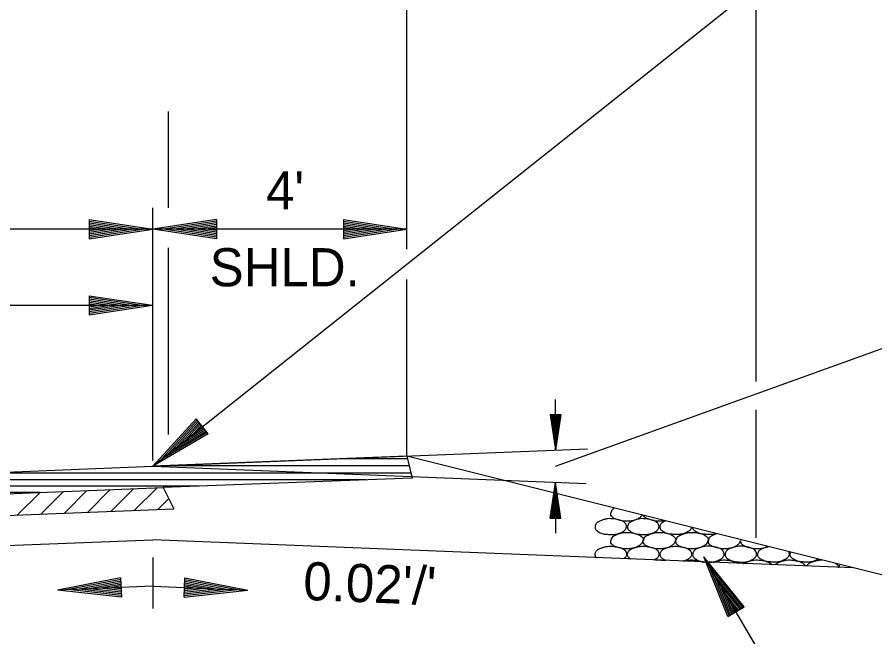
# Model space of a CAD drawing. Extents: x 1955768 to 1955917, y 566446 to 566546.
# Drawn here: x 1955845.04 to 1955858.54, y 566463.92 to 566473.67 of the extents above; entities that cross this region are included whole.
import ezdxf

# ---------------------------------------------------------------- set-up
doc = ezdxf.new("R2010")
doc.units = 0
doc.layers.add('R_Border', color=7, linetype='Continuous')
doc.layers.add('R_Grid', color=7, linetype='Continuous')

msp = doc.modelspace()

# ---------------------------------------------------------------- linework, layer by layer
at = {"layer": 'R_Border'}
for p, q in [((1955847.173, 566466.604), (1955854.018, 566466.878)), ((1955851.173, 566466.764), (1955847.173, 566466.604)), ((1955864.818, 566463.353), (1955851.173, 566466.764)), ((1955851.173, 566466.764), (1955851.259, 566466.42)), ((1955826.173, 566465.764), (1955847.173, 566466.604)), ((1955847.173, 566466.604), (1955853.996, 566466.331)), ((1955851.259, 566466.42), (1955847.339, 566466.271)), ((1955826.087, 566465.42), (1955847.339, 566466.271)), ((1955847.339, 566466.271), (1955847.506, 566465.937)), ((1955847.339, 566466.271), (1955847.506, 566465.937)), ((1955831.826, 566465.309), (1955847.506, 566465.937)), ((1955820.673, 566464.389), (1955847.173, 566465.449)), ((1955858.197, 566465.008), (1955847.173, 566465.449))]:
    msp.add_line(p, q, dxfattribs=at)
msp.add_lwpolyline([(1955853.512, 566466.604), (1955861.743, 566469.569)], dxfattribs=at)
at = {"layer": 'R_Grid'}
for p, q in [((1955851.173, 566470.021), (1955851.173, 566476.637)), ((1955856.673, 566467.941), (1955856.673, 566474.004)), ((1955847.423, 566470.669), (1955847.423, 566472.187)), ((1955847.173, 566466.694), (1955847.173, 566470.669)), ((1955846.173, 566470.486), (1955847.173, 566470.336)), ((1955846.173, 566470.486), (1955846.173, 566470.186)), ((1955846.173, 566470.461), (1955847.006, 566470.336)), ((1955848.174, 566470.486), (1955847.174, 566470.336)), ((1955848.174, 566470.461), (1955847.341, 566470.336)), ((1955848.174, 566470.486), (1955848.174, 566470.186)), ((1955850.173, 566470.486), (1955851.173, 566470.336)), ((1955850.173, 566470.486), (1955850.173, 566470.186)), ((1955850.173, 566470.461), (1955851.006, 566470.336)), ((1955847.173, 566470.336), (1955832.173, 566470.336)), ((1955846.173, 566470.436), (1955846.834, 566470.336)), ((1955846.173, 566470.411), (1955846.667, 566470.336)), ((1955846.173, 566470.385), (1955846.498, 566470.336)), ((1955846.173, 566470.36), (1955846.331, 566470.336)), ((1955846.173, 566470.186), (1955847.173, 566470.336)), ((1955846.173, 566470.287), (1955846.498, 566470.336)), ((1955846.173, 566470.237), (1955846.834, 566470.336)), ((1955846.173, 566470.211), (1955847.006, 566470.336)), ((1955846.173, 566470.262), (1955846.667, 566470.336)), ((1955846.173, 566470.313), (1955846.331, 566470.336)), ((1955851.173, 566470.336), (1955847.173, 566470.336)), ((1955848.174, 566470.186), (1955847.174, 566470.336)), ((1955848.174, 566470.211), (1955847.341, 566470.336)), ((1955848.174, 566470.436), (1955847.513, 566470.336)), ((1955848.174, 566470.237), (1955847.513, 566470.336)), ((1955848.174, 566470.411), (1955847.68, 566470.336)), ((1955848.174, 566470.262), (1955847.68, 566470.336)), ((1955848.174, 566470.385), (1955847.849, 566470.336)), ((1955848.174, 566470.287), (1955847.849, 566470.336)), ((1955848.174, 566470.36), (1955848.016, 566470.336)), ((1955848.174, 566470.313), (1955848.016, 566470.336)), ((1955850.799, 566470.336), (1955849.173, 566470.336)), ((1955850.173, 566470.436), (1955850.834, 566470.336)), ((1955850.173, 566470.411), (1955850.667, 566470.336)), ((1955850.173, 566470.385), (1955850.498, 566470.336)), ((1955850.173, 566470.36), (1955850.331, 566470.336)), ((1955850.173, 566470.186), (1955851.173, 566470.336)), ((1955850.173, 566470.287), (1955850.498, 566470.336)), ((1955850.173, 566470.237), (1955850.834, 566470.336)), ((1955850.173, 566470.211), (1955851.006, 566470.336)), ((1955850.173, 566470.262), (1955850.667, 566470.336)), ((1955850.173, 566470.313), (1955850.331, 566470.336)), ((1955847.423, 566467.104), (1955847.423, 566470.043)), ((1955851.173, 566466.762), (1955851.173, 566469.542)), ((1955846.171, 566469.289), (1955847.171, 566469.139)), ((1955846.171, 566469.289), (1955846.171, 566468.989)), ((1955846.171, 566469.264), (1955847.004, 566469.139)), ((1955846.171, 566469.238), (1955846.832, 566469.139)), ((1955839.673, 566469.139), (1955847.173, 566469.139)), ((1955846.171, 566469.213), (1955846.666, 566469.139)), ((1955846.171, 566469.187), (1955846.496, 566469.139)), ((1955846.171, 566469.162), (1955846.329, 566469.139)), ((1955846.171, 566468.989), (1955847.171, 566469.139)), ((1955846.171, 566469.09), (1955846.496, 566469.139)), ((1955846.171, 566469.039), (1955846.832, 566469.139)), ((1955846.171, 566469.014), (1955847.004, 566469.139)), ((1955846.171, 566469.064), (1955846.666, 566469.139)), ((1955846.171, 566469.115), (1955846.329, 566469.139)), ((1955853.512, 566466.858), (1955853.512, 566467.654)), ((1955856.673, 566465.48), (1955856.673, 566467.491)), ((1955847.857, 566467.349), (1955847.173, 566466.604)), ((1955848.045, 566467.115), (1955847.857, 566467.349)), ((1955853.428, 566467.42), (1955853.512, 566466.858)), ((1955853.428, 566467.42), (1955853.597, 566467.42)), ((1955853.428, 566467.42), (1955853.512, 566466.858)), ((1955853.428, 566467.42), (1955853.597, 566467.42)), ((1955853.442, 566467.42), (1955853.512, 566466.951)), ((1955853.442, 566467.42), (1955853.512, 566466.951)), ((1955853.456, 566467.42), (1955853.512, 566467.048)), ((1955853.456, 566467.42), (1955853.512, 566467.048)), ((1955853.47, 566467.42), (1955853.512, 566467.142)), ((1955853.47, 566467.42), (1955853.512, 566467.142)), ((1955853.485, 566467.42), (1955853.512, 566467.237)), ((1955853.485, 566467.42), (1955853.512, 566467.237)), ((1955853.499, 566467.42), (1955853.512, 566467.331)), ((1955853.499, 566467.42), (1955853.512, 566467.331)), ((1955853.597, 566467.42), (1955853.512, 566466.858)), ((1955853.54, 566467.42), (1955853.512, 566467.237)), ((1955853.568, 566467.42), (1955853.512, 566467.048)), ((1955853.583, 566467.42), (1955853.512, 566466.951)), ((1955853.554, 566467.42), (1955853.512, 566467.142)), ((1955853.526, 566467.42), (1955853.512, 566467.331)), ((1955853.597, 566467.42), (1955853.512, 566466.858)), ((1955853.54, 566467.42), (1955853.512, 566467.237)), ((1955853.568, 566467.42), (1955853.512, 566467.048)), ((1955853.583, 566467.42), (1955853.512, 566466.951)), ((1955853.554, 566467.42), (1955853.512, 566467.142)), ((1955853.526, 566467.42), (1955853.512, 566467.331)), ((1955847.872, 566467.329), (1955847.303, 566466.709)), ((1955847.888, 566467.309), (1955847.437, 566466.817)), ((1955847.904, 566467.29), (1955847.566, 566466.921)), ((1955847.92, 566467.27), (1955847.698, 566467.028)), ((1955847.936, 566467.25), (1955847.828, 566467.133)), ((1955847.966, 566467.214), (1955847.828, 566467.133)), ((1955848.045, 566467.115), (1955847.173, 566466.604)), ((1955848.029, 566467.135), (1955847.303, 566466.709)), ((1955848.013, 566467.154), (1955847.437, 566466.817)), ((1955847.998, 566467.174), (1955847.566, 566466.921)), ((1955847.981, 566467.194), (1955847.698, 566467.028)), ((1955851.183, 566466.724), (1955850.174, 566466.724)), ((1955851.211, 566466.614), (1955847.422, 566466.614)), ((1955850.532, 566466.393), (1955841.888, 566466.393)), ((1955851.239, 566466.498), (1955844.523, 566466.498)), ((1955847.904, 566466.293), (1955839.388, 566466.293)), ((1955847.241, 566466.267), (1955846.886, 566465.912)), ((1955853.428, 566465.788), (1955853.512, 566466.35)), ((1955853.428, 566465.788), (1955853.512, 566466.35)), ((1955853.442, 566465.788), (1955853.512, 566466.256)), ((1955853.442, 566465.788), (1955853.512, 566466.256)), ((1955853.597, 566465.788), (1955853.512, 566466.35)), ((1955853.597, 566465.788), (1955853.512, 566466.35)), ((1955853.512, 566466.35), (1955853.512, 566465.554)), ((1955853.583, 566465.788), (1955853.512, 566466.256)), ((1955853.583, 566465.788), (1955853.512, 566466.256)), ((1955845.395, 566466.193), (1955836.888, 566466.193)), ((1955845.399, 566466.193), (1955845.045, 566465.839)), ((1955845.768, 566466.208), (1955845.413, 566465.853)), ((1955846.136, 566466.222), (1955845.782, 566465.868)), ((1955846.504, 566466.237), (1955846.15, 566465.883)), ((1955846.872, 566466.252), (1955846.518, 566465.898)), ((1955853.456, 566465.788), (1955853.512, 566466.16)), ((1955853.456, 566465.788), (1955853.512, 566466.16)), ((1955853.568, 566465.788), (1955853.512, 566466.16)), ((1955853.568, 566465.788), (1955853.512, 566466.16)), ((1955847.426, 566466.098), (1955847.255, 566465.927)), ((1955853.47, 566465.788), (1955853.512, 566466.066)), ((1955853.47, 566465.788), (1955853.512, 566466.066)), ((1955853.554, 566465.788), (1955853.512, 566466.066)), ((1955853.554, 566465.788), (1955853.512, 566466.066)), ((1955853.485, 566465.788), (1955853.512, 566465.971)), ((1955853.485, 566465.788), (1955853.512, 566465.971)), ((1955853.499, 566465.788), (1955853.512, 566465.877)), ((1955853.499, 566465.788), (1955853.512, 566465.877)), ((1955853.54, 566465.788), (1955853.512, 566465.971)), ((1955853.54, 566465.788), (1955853.512, 566465.971)), ((1955853.526, 566465.788), (1955853.512, 566465.877)), ((1955853.526, 566465.788), (1955853.512, 566465.877)), ((1955853.428, 566465.788), (1955853.597, 566465.788)), ((1955853.428, 566465.788), (1955853.597, 566465.788)), ((1955856.224, 566464.242), (1955855.848, 566465.18)), ((1955856.483, 566464.393), (1955855.848, 566465.18)), ((1955847.173, 566465.167), (1955847.173, 566464.368)), ((1955856.245, 566464.254), (1955855.933, 566465.036)), ((1955856.461, 566464.38), (1955855.933, 566465.036)), ((1955846.667, 566464.847), (1955845.674, 566464.657)), ((1955846.668, 566464.822), (1955845.841, 566464.664)), ((1955846.669, 566464.796), (1955846.013, 566464.671)), ((1955846.67, 566464.771), (1955846.179, 566464.677)), ((1955846.667, 566464.847), (1955846.679, 566464.547)), ((1955847.666, 566464.547), (1955847.678, 566464.847)), ((1955847.675, 566464.771), (1955848.166, 566464.677)), ((1955847.676, 566464.796), (1955848.333, 566464.671)), ((1955847.677, 566464.822), (1955848.505, 566464.664)), ((1955847.678, 566464.847), (1955848.672, 566464.657)), ((1955856.439, 566464.368), (1955856.019, 566464.888)), ((1955856.267, 566464.267), (1955856.019, 566464.888)), ((1955847.173, 566464.717), (1955845.674, 566464.657)), ((1955846.679, 566464.547), (1955845.674, 566464.657)), ((1955846.678, 566464.572), (1955845.841, 566464.664)), ((1955846.677, 566464.598), (1955846.013, 566464.671)), ((1955846.676, 566464.623), (1955846.179, 566464.677)), ((1955846.671, 566464.746), (1955846.348, 566464.684)), ((1955846.675, 566464.648), (1955846.348, 566464.684)), ((1955846.672, 566464.721), (1955846.515, 566464.691)), ((1955846.674, 566464.674), (1955846.515, 566464.691)), ((1955847.173, 566464.717), (1955848.672, 566464.657)), ((1955847.666, 566464.547), (1955848.672, 566464.657)), ((1955847.667, 566464.572), (1955848.505, 566464.664)), ((1955847.668, 566464.598), (1955848.333, 566464.671)), ((1955847.669, 566464.623), (1955848.166, 566464.677)), ((1955847.67, 566464.649), (1955847.997, 566464.684)), ((1955847.671, 566464.674), (1955847.83, 566464.691)), ((1955847.673, 566464.721), (1955847.83, 566464.691)), ((1955847.674, 566464.746), (1955847.997, 566464.684)), ((1955856.289, 566464.28), (1955856.104, 566464.744)), ((1955856.418, 566464.355), (1955856.104, 566464.744)), ((1955856.396, 566464.342), (1955856.189, 566464.598)), ((1955856.311, 566464.293), (1955856.189, 566464.598)), ((1955856.224, 566464.242), (1955856.483, 566464.393)), ((1955856.374, 566464.329), (1955856.273, 566464.454)), ((1955856.333, 566464.305), (1955856.273, 566464.454))]:
    msp.add_line(p, q, dxfattribs=at)
for points in [[(1955847.173, 566466.604), (1955856.927, 566474.363), (1955858.401, 566474.363)], [(1955860.972, 566458.134), (1955859.972, 566458.134), (1955855.848, 566465.18)]]:
    msp.add_lwpolyline(points, dxfattribs=at)
for points in [[(1955854.64, 566465.74), (1955854.638, 566465.74), (1955854.613, 566465.74), (1955854.564, 566465.743), (1955854.5, 566465.762), (1955854.435, 566465.779), (1955854.389, 566465.819), (1955854.382, 566465.854), (1955854.382, 566465.868), (1955854.382, 566465.87)], [(1955854.39, 566465.87), (1955854.39, 566465.871), (1955854.391, 566465.888), (1955854.403, 566465.923), (1955854.427, 566465.94), (1955854.439, 566465.947)], [(1955854.384, 566465.78), (1955854.414, 566465.78), (1955854.481, 566465.771), (1955854.574, 566465.746), (1955854.625, 566465.7), (1955854.636, 566465.645), (1955854.612, 566465.601), (1955854.568, 566465.57), (1955854.508, 566465.544), (1955854.443, 566465.529), (1955854.377, 566465.53), (1955854.316, 566465.535), (1955854.247, 566465.54), (1955854.187, 566465.576), (1955854.138, 566465.608), (1955854.133, 566465.659), (1955854.15, 566465.709), (1955854.189, 566465.733), (1955854.236, 566465.754), (1955854.283, 566465.769), (1955854.334, 566465.78), (1955854.366, 566465.781), (1955854.384, 566465.78)], [(1955854.877, 566465.838), (1955854.872, 566465.827), (1955854.855, 566465.806), (1955854.818, 566465.78), (1955854.758, 566465.755), (1955854.695, 566465.74), (1955854.653, 566465.739), (1955854.64, 566465.74)], [(1955854.896, 566465.78), (1955854.926, 566465.78), (1955854.993, 566465.771), (1955855.086, 566465.746), (1955855.137, 566465.7), (1955855.148, 566465.645), (1955855.124, 566465.601), (1955855.08, 566465.57), (1955855.02, 566465.544), (1955854.955, 566465.529), (1955854.889, 566465.53), (1955854.828, 566465.535), (1955854.759, 566465.54), (1955854.699, 566465.576), (1955854.65, 566465.608), (1955854.645, 566465.659), (1955854.662, 566465.709), (1955854.701, 566465.733), (1955854.748, 566465.754), (1955854.795, 566465.769), (1955854.846, 566465.78), (1955854.878, 566465.781), (1955854.896, 566465.78)], [(1955855.152, 566465.74), (1955855.15, 566465.74), (1955855.125, 566465.74), (1955855.076, 566465.743), (1955855.012, 566465.762), (1955854.947, 566465.779), (1955854.91, 566465.811), (1955854.901, 566465.831), (1955854.901, 566465.832)], [(1955855.237, 566465.748), (1955855.222, 566465.744), (1955855.194, 566465.739), (1955855.165, 566465.739), (1955855.152, 566465.74)], [(1955855.654, 566465.644), (1955855.65, 566465.627), (1955855.633, 566465.599), (1955855.592, 566465.57), (1955855.532, 566465.544), (1955855.467, 566465.529), (1955855.401, 566465.53), (1955855.34, 566465.535), (1955855.271, 566465.54), (1955855.211, 566465.576), (1955855.162, 566465.608), (1955855.157, 566465.659), (1955855.174, 566465.709), (1955855.209, 566465.731), (1955855.234, 566465.742), (1955855.243, 566465.746)], [(1955856.043, 566465.546), (1955856.017, 566465.538), (1955855.977, 566465.529), (1955855.913, 566465.53), (1955855.852, 566465.535), (1955855.783, 566465.54), (1955855.723, 566465.576), (1955855.678, 566465.605), (1955855.672, 566465.633), (1955855.672, 566465.639)], [(1955854.39, 566465.436), (1955854.39, 566465.437), (1955854.391, 566465.454), (1955854.404, 566465.492), (1955854.445, 566465.517), (1955854.492, 566465.538), (1955854.539, 566465.553), (1955854.59, 566465.564), (1955854.622, 566465.565), (1955854.64, 566465.564)], [(1955854.64, 566465.564), (1955854.642, 566465.564), (1955854.644, 566465.564), (1955854.646, 566465.564)], [(1955854.646, 566465.564), (1955854.676, 566465.564), (1955854.743, 566465.555), (1955854.832, 566465.529), (1955854.889, 566465.481), (1955854.895, 566465.448), (1955854.897, 566465.436), (1955854.896, 566465.436)], [(1955854.902, 566465.436), (1955854.902, 566465.437), (1955854.903, 566465.454), (1955854.916, 566465.492), (1955854.957, 566465.517), (1955855.004, 566465.538), (1955855.051, 566465.553), (1955855.102, 566465.564), (1955855.134, 566465.565), (1955855.152, 566465.564)], [(1955855.152, 566465.564), (1955855.154, 566465.564), (1955855.156, 566465.564), (1955855.158, 566465.564)], [(1955855.158, 566465.564), (1955855.188, 566465.564), (1955855.255, 566465.555), (1955855.344, 566465.529), (1955855.401, 566465.481), (1955855.407, 566465.448), (1955855.409, 566465.436), (1955855.408, 566465.436)], [(1955855.414, 566465.436), (1955855.414, 566465.437), (1955855.415, 566465.454), (1955855.428, 566465.492), (1955855.469, 566465.517), (1955855.516, 566465.538), (1955855.563, 566465.553), (1955855.614, 566465.564), (1955855.646, 566465.565), (1955855.664, 566465.564)], [(1955855.664, 566465.564), (1955855.666, 566465.564), (1955855.668, 566465.564), (1955855.67, 566465.564)], [(1955855.67, 566465.564), (1955855.7, 566465.564), (1955855.767, 566465.555), (1955855.856, 566465.529), (1955855.913, 566465.481), (1955855.919, 566465.448), (1955855.921, 566465.436), (1955855.92, 566465.436)], [(1955855.926, 566465.436), (1955855.926, 566465.437), (1955855.927, 566465.454), (1955855.94, 566465.492), (1955855.981, 566465.517), (1955856.018, 566465.534), (1955856.041, 566465.542), (1955856.05, 566465.545)], [(1955854.16, 566465.164), (1955854.154, 566465.171), (1955854.136, 566465.188), (1955854.133, 566465.225), (1955854.15, 566465.275), (1955854.189, 566465.299), (1955854.236, 566465.32), (1955854.283, 566465.335), (1955854.334, 566465.346), (1955854.366, 566465.347), (1955854.384, 566465.346)], [(1955854.64, 566465.306), (1955854.638, 566465.306), (1955854.613, 566465.306), (1955854.564, 566465.309), (1955854.5, 566465.328), (1955854.435, 566465.345), (1955854.389, 566465.385), (1955854.382, 566465.42), (1955854.382, 566465.434), (1955854.382, 566465.436)], [(1955854.384, 566465.346), (1955854.414, 566465.346), (1955854.481, 566465.337), (1955854.574, 566465.312), (1955854.625, 566465.266), (1955854.636, 566465.211), (1955854.614, 566465.171), (1955854.593, 566465.152), (1955854.585, 566465.147)], [(1955854.884, 566465.436), (1955854.884, 566465.434), (1955854.885, 566465.411), (1955854.862, 566465.377), (1955854.818, 566465.346), (1955854.758, 566465.321), (1955854.695, 566465.306), (1955854.653, 566465.305), (1955854.64, 566465.306)], [(1955854.7, 566465.143), (1955854.682, 566465.154), (1955854.65, 566465.176), (1955854.645, 566465.225), (1955854.662, 566465.275), (1955854.701, 566465.299), (1955854.748, 566465.32), (1955854.795, 566465.335), (1955854.846, 566465.346), (1955854.878, 566465.347), (1955854.896, 566465.346)], [(1955855.152, 566465.306), (1955855.15, 566465.306), (1955855.125, 566465.306), (1955855.076, 566465.309), (1955855.012, 566465.328), (1955854.947, 566465.345), (1955854.901, 566465.385), (1955854.894, 566465.42), (1955854.894, 566465.434), (1955854.894, 566465.436)], [(1955854.896, 566465.346), (1955854.926, 566465.346), (1955854.993, 566465.337), (1955855.086, 566465.312), (1955855.137, 566465.266), (1955855.148, 566465.211), (1955855.124, 566465.167), (1955855.091, 566465.143), (1955855.071, 566465.132), (1955855.063, 566465.128)], [(1955855.396, 566465.436), (1955855.396, 566465.434), (1955855.397, 566465.411), (1955855.374, 566465.377), (1955855.33, 566465.346), (1955855.27, 566465.321), (1955855.207, 566465.306), (1955855.165, 566465.305), (1955855.152, 566465.306)], [(1955855.25, 566465.121), (1955855.239, 566465.126), (1955855.206, 566465.145), (1955855.162, 566465.174), (1955855.157, 566465.225), (1955855.174, 566465.275), (1955855.213, 566465.299), (1955855.26, 566465.32), (1955855.307, 566465.335), (1955855.358, 566465.346), (1955855.39, 566465.347), (1955855.408, 566465.346)], [(1955855.664, 566465.306), (1955855.662, 566465.306), (1955855.637, 566465.306), (1955855.588, 566465.309), (1955855.524, 566465.328), (1955855.459, 566465.345), (1955855.413, 566465.385), (1955855.406, 566465.42), (1955855.406, 566465.434), (1955855.406, 566465.436)], [(1955855.408, 566465.346), (1955855.438, 566465.346), (1955855.505, 566465.337), (1955855.598, 566465.312), (1955855.649, 566465.266), (1955855.66, 566465.211), (1955855.636, 566465.167), (1955855.592, 566465.136), (1955855.556, 566465.119), (1955855.53, 566465.111), (1955855.525, 566465.11)], [(1955855.908, 566465.436), (1955855.908, 566465.434), (1955855.909, 566465.411), (1955855.886, 566465.377), (1955855.842, 566465.346), (1955855.782, 566465.321), (1955855.719, 566465.306), (1955855.677, 566465.305), (1955855.664, 566465.306)], [(1955855.92, 566465.346), (1955855.95, 566465.346), (1955856.017, 566465.337), (1955856.11, 566465.312), (1955856.161, 566465.266), (1955856.172, 566465.211), (1955856.148, 566465.167), (1955856.104, 566465.136), (1955856.044, 566465.11), (1955855.979, 566465.095), (1955855.913, 566465.096), (1955855.852, 566465.101), (1955855.783, 566465.106), (1955855.723, 566465.142), (1955855.674, 566465.174), (1955855.669, 566465.225), (1955855.686, 566465.275), (1955855.725, 566465.299), (1955855.772, 566465.32), (1955855.819, 566465.335), (1955855.87, 566465.346), (1955855.902, 566465.347), (1955855.92, 566465.346)], [(1955856.176, 566465.306), (1955856.174, 566465.306), (1955856.149, 566465.306), (1955856.1, 566465.309), (1955856.036, 566465.328), (1955855.971, 566465.345), (1955855.925, 566465.385), (1955855.918, 566465.42), (1955855.918, 566465.434), (1955855.918, 566465.436)], [(1955856.42, 566465.436), (1955856.42, 566465.434), (1955856.421, 566465.411), (1955856.398, 566465.377), (1955856.354, 566465.346), (1955856.294, 566465.321), (1955856.231, 566465.306), (1955856.189, 566465.305), (1955856.176, 566465.306)], [(1955856.432, 566465.346), (1955856.462, 566465.346), (1955856.529, 566465.337), (1955856.622, 566465.312), (1955856.673, 566465.266), (1955856.684, 566465.211), (1955856.66, 566465.167), (1955856.616, 566465.136), (1955856.556, 566465.11), (1955856.491, 566465.095), (1955856.425, 566465.096), (1955856.364, 566465.101), (1955856.295, 566465.106), (1955856.235, 566465.142), (1955856.186, 566465.174), (1955856.181, 566465.225), (1955856.198, 566465.275), (1955856.237, 566465.299), (1955856.284, 566465.32), (1955856.331, 566465.335), (1955856.382, 566465.346), (1955856.414, 566465.347), (1955856.432, 566465.346)], [(1955856.688, 566465.306), (1955856.686, 566465.306), (1955856.661, 566465.306), (1955856.612, 566465.309), (1955856.548, 566465.328), (1955856.483, 566465.345), (1955856.437, 566465.385), (1955856.43, 566465.42), (1955856.43, 566465.434), (1955856.43, 566465.436)], [(1955856.856, 566465.343), (1955856.842, 566465.336), (1955856.8, 566465.319), (1955856.743, 566465.306), (1955856.701, 566465.305), (1955856.688, 566465.306)], [(1955857.181, 566465.262), (1955857.183, 566465.258), (1955857.189, 566465.246), (1955857.196, 566465.211), (1955857.172, 566465.167), (1955857.128, 566465.136), (1955857.068, 566465.11), (1955857.003, 566465.095), (1955856.937, 566465.096), (1955856.876, 566465.101), (1955856.807, 566465.106), (1955856.747, 566465.142), (1955856.698, 566465.174), (1955856.693, 566465.225), (1955856.71, 566465.275), (1955856.749, 566465.299), (1955856.796, 566465.32), (1955856.836, 566465.333), (1955856.862, 566465.339), (1955856.868, 566465.34)], [(1955857.651, 566465.144), (1955857.65, 566465.144), (1955857.629, 566465.131), (1955857.58, 566465.11), (1955857.515, 566465.095), (1955857.449, 566465.096), (1955857.388, 566465.101), (1955857.319, 566465.106), (1955857.259, 566465.142), (1955857.21, 566465.174), (1955857.206, 566465.219), (1955857.211, 566465.243), (1955857.216, 566465.253)], [(1955855.092, 566465.127), (1955855.094, 566465.127), (1955855.113, 566465.131), (1955855.134, 566465.131), (1955855.152, 566465.13)], [(1955855.152, 566465.13), (1955855.154, 566465.13), (1955855.156, 566465.13), (1955855.158, 566465.13)], [(1955855.158, 566465.13), (1955855.185, 566465.13), (1955855.212, 566465.127), (1955855.239, 566465.121)], [(1955855.534, 566465.109), (1955855.546, 566465.113), (1955855.571, 566465.12), (1955855.614, 566465.13), (1955855.646, 566465.131), (1955855.664, 566465.13)], [(1955855.664, 566465.13), (1955855.666, 566465.13), (1955855.668, 566465.13), (1955855.67, 566465.13)], [(1955855.67, 566465.13), (1955855.7, 566465.13), (1955855.756, 566465.123), (1955855.808, 566465.108), (1955855.832, 566465.098)], [(1955855.996, 566465.091), (1955856.005, 566465.095), (1955856.033, 566465.106), (1955856.075, 566465.119), (1955856.126, 566465.13), (1955856.158, 566465.131), (1955856.176, 566465.13)], [(1955856.176, 566465.13), (1955856.178, 566465.13), (1955856.18, 566465.13), (1955856.182, 566465.13)], [(1955856.182, 566465.13), (1955856.212, 566465.13), (1955856.279, 566465.121), (1955856.346, 566465.1), (1955856.382, 566465.078), (1955856.387, 566465.075)], [(1955856.475, 566465.072), (1955856.481, 566465.076), (1955856.501, 566465.087), (1955856.54, 566465.104), (1955856.587, 566465.119), (1955856.638, 566465.13), (1955856.67, 566465.131), (1955856.688, 566465.13)], [(1955856.688, 566465.13), (1955856.69, 566465.13), (1955856.692, 566465.13), (1955856.694, 566465.13)], [(1955856.694, 566465.13), (1955856.724, 566465.13), (1955856.791, 566465.121), (1955856.871, 566465.097), (1955856.912, 566465.066), (1955856.923, 566465.054)], [(1955856.967, 566465.052), (1955856.978, 566465.067), (1955857.005, 566465.083), (1955857.052, 566465.104), (1955857.099, 566465.119), (1955857.15, 566465.13), (1955857.182, 566465.131), (1955857.2, 566465.13)], [(1955857.2, 566465.13), (1955857.202, 566465.13), (1955857.204, 566465.13), (1955857.206, 566465.13)], [(1955857.206, 566465.13), (1955857.236, 566465.13), (1955857.303, 566465.121), (1955857.392, 566465.095), (1955857.437, 566465.056), (1955857.449, 566465.033), (1955857.449, 566465.033)], [(1955857.468, 566465.032), (1955857.47, 566465.039), (1955857.484, 566465.063), (1955857.517, 566465.083), (1955857.564, 566465.104), (1955857.611, 566465.119), (1955857.662, 566465.13), (1955857.694, 566465.131), (1955857.712, 566465.13)], [(1955857.923, 566465.076), (1955857.939, 566465.065), (1955857.959, 566465.046), (1955857.966, 566465.02), (1955857.967, 566465.012)], [(1955857.975, 566465.012), (1955857.976, 566465.026), (1955857.983, 566465.043), (1955857.994, 566465.056), (1955857.996, 566465.058)]]:
    msp.add_open_spline(points, degree=3, dxfattribs=at)

# ---------------------------------------------------------------- texts
at = {"layer": 'R_Border'}
for s, p in [("4'", (1955848.956, 566470.646)), ('SHLD.', (1955848.069, 566469.437))]:
    msp.add_text(s, height=0.6, dxfattribs=at).set_placement(p)
msp.add_text("0.02'/'", height=0.6, rotation=357.7094, dxfattribs=at).set_placement((1955849.533, 566464.503))

doc.saveas('drawing.dxf')
